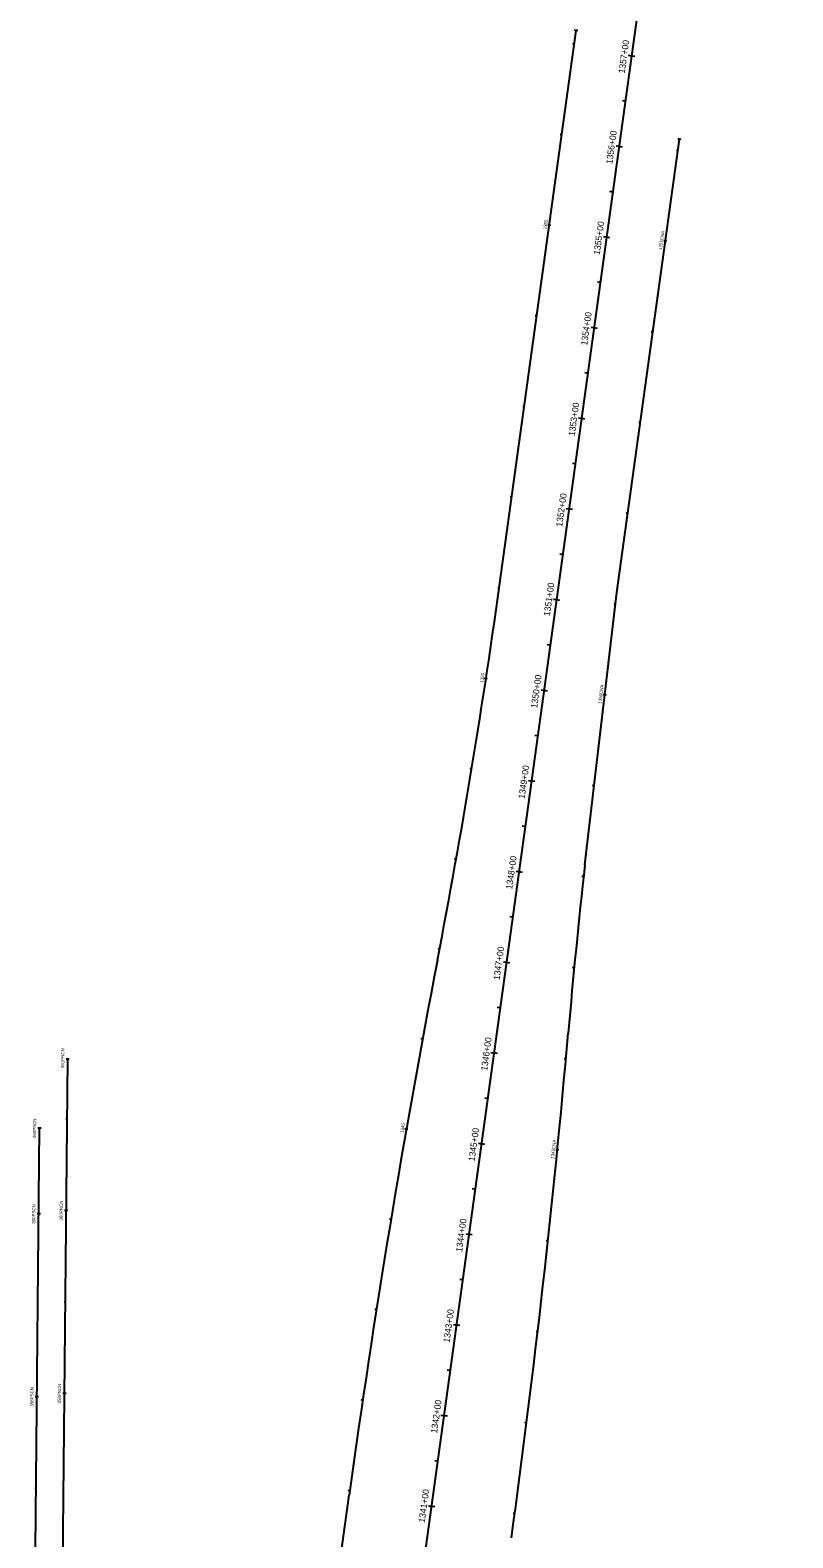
# Model space of a CAD drawing. Extents: x 596007 to 607538, y 326212 to 405053.
# Drawn here: x 602005 to 602838, y 358460 to 360108 of the extents above; entities that cross this region are included whole.
import ezdxf

# ---------------------------------------------------------------- set-up
doc = ezdxf.new("R2010")
doc.units = 0
for name, color, linetype in [('P_ALI', 7, 'Continuous'), ('P_ALI_200', 7, 'Continuous'), ('P_ALI_200_Sta', 7, 'Continuous'), ('P_ALI_200_Tic', 7, 'Continuous')]:
    doc.layers.add(name, color=color, linetype=linetype)

msp = doc.modelspace()

# ---------------------------------------------------------------- linework, layer by layer
at = {"layer": 'P_ALI'}
for points in [[(602519.8, 359514.1), (602601.7, 360107.5)], [(602646.2, 359493.2), (602714.5, 359988.5)], [(602611.2, 359195.7), (602646.2, 359493.2)], [(602036.4, 357988.7), (602046.1, 358983.5)], [(602249, 357749.5), (602353.6, 358506.9)]]:
    msp.add_lwpolyline(points, dxfattribs=at)
for centre, radius, start, end in [((594495.9, 360621.5), 8100, 349.11109, 352.14213), ((610662.2, 358306.9), 8100, 173.70013, 175.00722), ((613448.4, 356975.7), 11200, 169.11109, 172.14213), ((591535.1, 359977.9), 11100, 352.14213, 355.00722)]:
    msp.add_arc(centre, radius, start, end, dxfattribs=at)
at = {"layer": 'P_ALI_200'}
for points in [[(602352.9, 357836.4), (602838.4, 361354.3)], [(602007.1, 358064.4), (602015.3, 358907.9)]]:
    msp.add_lwpolyline(points, dxfattribs=at)
at = {"layer": 'P_ALI_200_Sta'}
for points in [[(602601.7, 360107.5), (602600, 360107.7)], [(602601.7, 360107.5), (602601.7, 360107.5)], [(602603.5, 360107.2), (602601.7, 360107.5)], [(602599.7, 360092.6), (602597.9, 360092.9)], [(602662.5, 360079.5), (602659, 360080)], [(602662.5, 360079.5), (602662.5, 360079.5)], [(602665.9, 360079.1), (602662.5, 360079.5)], [(602655.6, 360030), (602652.2, 360030.5)], [(602586, 359993.6), (602584.3, 359993.8)], [(602648.8, 359980.5), (602645.3, 359981)], [(602714.5, 359988.5), (602712.8, 359988.7)], [(602714.5, 359988.5), (602714.5, 359988.5)], [(602716.2, 359988.2), (602714.5, 359988.5)], [(602648.8, 359980.5), (602648.8, 359980.5)], [(602652.3, 359980), (602648.8, 359980.5)], [(602712.8, 359976.1), (602711.1, 359976.3)], [(602642, 359930.9), (602638.5, 359931.4)], [(602572.3, 359894.5), (602570.6, 359894.8)], [(602572.3, 359894.5), (602572.3, 359894.5)], [(602574.1, 359894.3), (602572.3, 359894.5)], [(602635.1, 359881.4), (602631.7, 359881.9)], [(602635.1, 359881.4), (602635.1, 359881.4)], [(602638.6, 359880.9), (602635.1, 359881.4)], [(602699.1, 359877), (602697.4, 359877.3)], [(602699.1, 359877), (602699.1, 359877)], [(602700.9, 359876.8), (602699.1, 359877)], [(602628.3, 359831.9), (602624.8, 359832.4)], [(602558.7, 359795.5), (602556.9, 359795.7)], [(602621.5, 359782.4), (602618, 359782.8)], [(602621.5, 359782.4), (602621.5, 359782.4)], [(602624.9, 359781.9), (602621.5, 359782.4)], [(602685.5, 359778), (602683.7, 359778.2)], [(602614.6, 359732.8), (602611.2, 359733.3)], [(602545, 359696.4), (602543.3, 359696.6)], [(602607.8, 359683.3), (602604.3, 359683.8)], [(602607.8, 359683.3), (602607.8, 359683.3)], [(602611.3, 359682.8), (602607.8, 359683.3)], [(602671.8, 359678.9), (602670.1, 359679.1)], [(602600.9, 359633.8), (602597.5, 359634.2)], [(602531.3, 359597.3), (602529.6, 359597.6)], [(602594.1, 359584.2), (602590.6, 359584.7)], [(602594.1, 359584.2), (602594.1, 359584.2)], [(602597.6, 359583.8), (602594.1, 359584.2)], [(602658.1, 359579.8), (602656.4, 359580.1)], [(602587.3, 359534.7), (602583.8, 359535.2)], [(602517.6, 359498.3), (602515.9, 359498.5)], [(602580.4, 359485.2), (602577, 359485.6)], [(602580.4, 359485.2), (602580.4, 359485.2)], [(602583.9, 359484.7), (602580.4, 359485.2)], [(602644.7, 359480.7), (602643, 359480.9)], [(602573.6, 359435.6), (602570.1, 359436.1)], [(602503.1, 359399.3), (602501.4, 359399.6)], [(602503.1, 359399.3), (602503.1, 359399.3)], [(602504.9, 359399.1), (602503.1, 359399.3)], [(602566.8, 359386.1), (602563.3, 359386.6)], [(602566.8, 359386.1), (602566.8, 359386.1)], [(602570.2, 359385.6), (602566.8, 359386.1)], [(602633, 359381.4), (602631.3, 359381.6)], [(602633, 359381.4), (602633, 359381.4)], [(602634.7, 359381.2), (602633, 359381.4)], [(602559.9, 359336.6), (602556.5, 359337.1)], [(602487.5, 359300.6), (602485.7, 359300.9)], [(602553.1, 359287), (602549.6, 359287.5)], [(602553.1, 359287), (602553.1, 359287)], [(602556.6, 359286.6), (602553.1, 359287)], [(602621.3, 359282.1), (602619.6, 359282.3)], [(602546.3, 359237.5), (602542.8, 359238)], [(602470.5, 359202), (602468.8, 359202.3)], [(602539.4, 359188), (602536, 359188.5)], [(602539.4, 359188), (602539.4, 359188)], [(602542.9, 359187.5), (602539.4, 359188)], [(602609.7, 359182.8), (602608, 359183)], [(602532.6, 359138.5), (602529.1, 359138.9)], [(602452.4, 359103.7), (602450.7, 359104)], [(602525.8, 359088.9), (602522.3, 359089.4)], [(602525.8, 359088.9), (602525.8, 359088.9)], [(602529.2, 359088.4), (602525.8, 359088.9)], [(602599.5, 359083.3), (602597.8, 359083.5)], [(602518.9, 359039.4), (602515.5, 359039.9)], [(602433.9, 359005.4), (602432.1, 359005.7)], [(602046.1, 358983.5), (602044.3, 358983.5)], [(602046.1, 358983.5), (602046.1, 358983.5)], [(602047.8, 358983.5), (602046.1, 358983.5)], [(602512.1, 358989.9), (602508.6, 358990.3)], [(602512.1, 358989.9), (602512.1, 358989.9)], [(602515.6, 358989.4), (602512.1, 358989.9)], [(602590.5, 358983.7), (602588.7, 358983.9)], [(602505.2, 358940.3), (602501.8, 358940.8)], [(602015.3, 358907.9), (602013.6, 358907.9)], [(602015.3, 358907.9), (602015.3, 358907.9)], [(602017.1, 358907.9), (602015.3, 358907.9)], [(602416.2, 358907), (602414.4, 358907.3)], [(602416.2, 358907), (602416.2, 358907)], [(602417.9, 358906.7), (602416.2, 358907)], [(602498.4, 358890.8), (602494.9, 358891.3)], [(602498.4, 358890.8), (602498.4, 358890.8)], [(602501.9, 358890.3), (602498.4, 358890.8)], [(602581.1, 358884.2), (602579.3, 358884.3)], [(602581.1, 358884.2), (602581.1, 358884.2)], [(602582.8, 358884), (602581.1, 358884.2)], [(602491.6, 358841.3), (602488.1, 358841.8)], [(602014.4, 358814.3), (602012.7, 358814.3)], [(602014.4, 358814.3), (602014.4, 358814.3)], [(602016.2, 358814.3), (602014.4, 358814.3)], [(602044.5, 358817.9), (602042.7, 358817.9)], [(602044.5, 358817.9), (602044.5, 358817.9)], [(602046.2, 358817.8), (602044.5, 358817.9)], [(602399.4, 358808.4), (602397.6, 358808.7)], [(602484.7, 358791.7), (602481.3, 358792.2)], [(602484.7, 358791.7), (602484.7, 358791.7)], [(602488.2, 358791.3), (602484.7, 358791.7)], [(602570.8, 358784.7), (602569, 358784.9)], [(602477.9, 358742.2), (602474.4, 358742.7)], [(602383.4, 358709.7), (602381.7, 358710)], [(602471.1, 358692.7), (602467.6, 358693.2)], [(602471.1, 358692.7), (602471.1, 358692.7)], [(602474.5, 358692.2), (602471.1, 358692.7)], [(602559.6, 358685.3), (602557.8, 358685.5)], [(602464.2, 358643.2), (602460.8, 358643.6)], [(602012.5, 358614.3), (602010.7, 358614.4)], [(602012.5, 358614.3), (602012.5, 358614.3)], [(602014.2, 358614.3), (602012.5, 358614.3)], [(602042.5, 358617.9), (602040.8, 358617.9)], [(602042.5, 358617.9), (602042.5, 358617.9)], [(602044.3, 358617.9), (602042.5, 358617.9)], [(602368.4, 358610.8), (602366.7, 358611.1)], [(602457.4, 358593.6), (602453.9, 358594.1)], [(602457.4, 358593.6), (602457.4, 358593.6)], [(602460.9, 358593.1), (602457.4, 358593.6)], [(602547.5, 358586.1), (602545.7, 358586.3)], [(602450.6, 358544.1), (602447.1, 358544.6)], [(602354.2, 358511.8), (602352.5, 358512.1)], [(602443.7, 358494.6), (602440.3, 358495)], [(602443.7, 358494.6), (602443.7, 358494.6)], [(602447.2, 358494.1), (602443.7, 358494.6)], [(602534.5, 358486.9), (602532.8, 358487.1)]]:
    msp.add_lwpolyline(points, dxfattribs=at)
at = {"layer": 'P_ALI_200_Tic'}
for points in [[(602045.4, 358917.9), (602044.2, 358917.9)], [(602013.4, 358714.3), (602012.2, 358714.3)], [(602043.5, 358717.9), (602042.2, 358717.9)], [(602011.5, 358514.3), (602010.3, 358514.4)], [(602041.5, 358517.9), (602040.3, 358517.9)]]:
    msp.add_lwpolyline(points, dxfattribs=at)

# ---------------------------------------------------------------- texts
at = {"layer": 'P_ALI_200_Sta'}
for s, height, rotation, p in [('1357+00', 7, 82.1421, (602654.7, 360060.1)), ('1356+00', 7, 82.1421, (602641.1, 359961.1)), ('1356CNA', 0.0000000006, 82.1421, (602712, 359988.8)), ('1355', 3.5, 82.1421, (602569.2, 359889.9)), ('1355+00', 7, 82.1421, (602627.4, 359862)), ('1355CNA', 3.5, 82.1421, (602695.3, 359867.4)), ('1354+00', 7, 82.1421, (602613.7, 359762.9)), ('1353+00', 7, 82.1421, (602600.1, 359663.9)), ('1352+00', 7, 82.1421, (602586.4, 359564.8)), ('1351+00', 7, 82.1421, (602572.9, 359467.2)), ('1350', 3.5, 81.3215, (602499.9, 359394.6)), ('1350+00', 7, 82.1421, (602559, 359366.5)), ('1350CNA', 3.5, 83.2889, (602629.3, 359371.6)), ('1349+00', 7, 82.1421, (602545.4, 359267.6)), ('1348+00', 7, 82.1421, (602531.7, 359168.6)), ('1347+00', 7, 82.1421, (602518, 359069.5)), ('361PNCN', 3.5, 89.4437, (602042.2, 358973.5)), ('1346+00', 7, 82.1421, (602504.4, 358970.4)), ('360PSCN', 3.5, 89.4437, (602011.5, 358897)), ('1345', 3.5, 80.0704, (602412.8, 358902.5)), ('1345+00', 7, 82.1421, (602490.7, 358871.4)), ('1345CNA', 3.5, 84.3453, (602577.6, 358874.4)), ('360PNCN', 3.5, 89.4437, (602040.6, 358807)), ('360PSCN', 3.5, 89.4437, (602010.6, 358803.4)), ('1344+00', 7, 82.1421, (602477, 358772.3)), ('1343+00', 7, 82.1421, (602463.3, 358673.3)), ('358PSCN', 3.5, 89.4437, (602008.6, 358603.6)), ('358PNCN', 3.5, 89.4437, (602038.7, 358607.1)), ('1342+00', 7, 82.1421, (602449.7, 358574.2)), ('1341+00', 7, 82.1421, (602436.2, 358476.6))]:
    msp.add_text(s, height=height, rotation=rotation, dxfattribs=at).set_placement(p)

doc.saveas('drawing.dxf')
